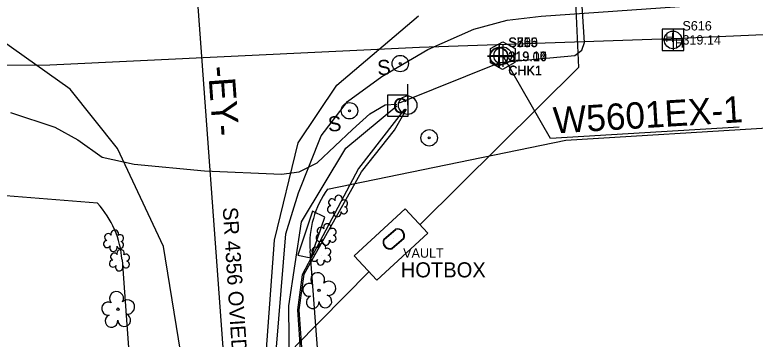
# Model space of a CAD drawing. Extents: x 2110969 to 2113691, y 670003 to 672285.
# Drawn here: x 2112129.5 to 2112326.2, y 670380.3 to 670466.5 of the extents above; entities that cross this region are included whole.
import ezdxf

# ---------------------------------------------------------------- set-up
doc = ezdxf.new("R2010")
doc.units = 0
for name, color, linetype in [('Cogo Default Point CELL', 7, 'Continuous'), ('COGO Default Point Elevation', 7, 'Continuous'), ('COGO Default Point Number', 7, 'Continuous'), ('Default', 7, 'Continuous'), ('Default Symbol CELL', 7, 'Continuous'), ('Default Symbol Cogo Comment', 7, 'Continuous'), ('Default Symbol Cogo Elevation', 7, 'Continuous'), ('Default Symbol Cogo Number', 7, 'Continuous'), ('Exist Horizontal Alignment', 7, 'Continuous'), ('Exist Horizontal Alignment Direction Label', 7, 'Continuous'), ('Exist Horizontal Baseline Alignment Station Label', 7, 'Continuous'), ('Exist Other Culture Anchor (Guy Wire) CELL', 7, 'Continuous'), ('Exist Other Culture Sign Text', 7, 'Continuous'), ('Exist Right of Way Line', 7, 'Continuous'), ('Exist Right of Way Symbol CELL', 7, 'Continuous'), ('Exist Roads EOP', 7, 'Continuous'), ('Exist Roads EOP Text', 7, 'Continuous'), ('Exist Utilities Power Pole CELL', 7, 'Continuous'), ('Exist Utilities Power UG Cable SUE LOS B', 7, 'Continuous'), ('Exist Utilities Telephone Hand Hole CELL', 7, 'Continuous'), ('Exist Utilities Telephone UG Cable SUE LOS B', 7, 'Continuous'), ('Exist Utilities Telephone UG FO SUE LOS B', 7, 'Continuous'), ('Exist Utilities TV Pedestal CELL', 7, 'Continuous'), ('Exist Utilities TV UG Cable SUE LOS B', 7, 'Continuous'), ('Exist Utilities Water Meter CELL', 7, 'Continuous'), ('Exist Utilities Water Meter Cogo Comment', 7, 'Continuous'), ('Exist Utilities Water Meter Text', 7, 'Continuous'), ('Exist Utilities Water UG Line SUE LOS B', 7, 'Continuous'), ('Exist Utilities Water UG Line SUE LOS C', 7, 'Continuous'), ('Exist Vegetation Hedge Row', 7, 'Continuous'), ('Exist Vegetation Shrub CELL', 7, 'Continuous'), ('Exist Vegetation Tree CELL', 7, 'Continuous')]:
    doc.layers.add(name, color=color, linetype=linetype)

msp = doc.modelspace()

# ---------------------------------------------------------------- linework, layer by layer
at = {"layer": 'Cogo Default Point CELL'}
for points in [[(2112304.4, 670462.84), (2112304.4, 670459.84)], [(2112301.4, 670459.84), (2112304.4, 670459.84)], [(2112304.4, 670459.84), (2112307.4, 670459.84)], [(2112304.4, 670459.84), (2112304.4, 670456.84)], [(2112259.14, 670458.65), (2112259.14, 670455.65)], [(2112256.14, 670455.65), (2112259.14, 670455.65)], [(2112259.14, 670455.65), (2112262.14, 670455.65)], [(2112259.14, 670455.65), (2112259.14, 670452.65)]]:
    msp.add_lwpolyline(points, dxfattribs=at)
for centre in [(2112304.4, 670459.84), (2112259.14, 670455.65)]:
    msp.add_circle(centre, 2.34, dxfattribs=at)
at = {"layer": 'Default'}
for centre, radius in [((2112231.9, 670453.55), 2.18), ((2112231.9, 670453.55), 0.24), ((2112218.41, 670440.99), 2.18), ((2112218.41, 670440.99), 0.24)]:
    msp.add_circle(centre, radius, dxfattribs=at)
at = {"layer": 'Default Symbol CELL'}
for points in [[(2112258.08, 670458.45), (2112258.08, 670452.45), (2112258.08, 670455.45), (2112261.08, 670455.45), (2112255.08, 670455.45)], [(2112258.13, 670458.52), (2112258.13, 670452.52), (2112258.13, 670455.52), (2112261.13, 670455.52), (2112255.13, 670455.52)], [(2112258.16, 670458.49), (2112258.16, 670452.49), (2112258.16, 670455.49), (2112261.16, 670455.49), (2112255.16, 670455.49)], [(2112258.17, 670458.4), (2112258.17, 670452.4), (2112258.17, 670455.4), (2112261.17, 670455.4), (2112255.17, 670455.4)]]:
    msp.add_lwpolyline(points, dxfattribs=at)
for centre in [(2112258.08, 670455.45), (2112258.13, 670455.52), (2112258.16, 670455.49), (2112258.17, 670455.4)]:
    msp.add_circle(centre, 2.34, dxfattribs=at)
at = {"layer": 'Exist Horizontal Alignment'}
msp.add_line((2112177.47, 670477.33), (2112189.48, 670313.22), dxfattribs=at)
at = {"layer": 'Exist Horizontal Baseline Alignment Station Label'}
for p, q in [((2112259.14, 670455.65), (2112259.14, 670455.65)), ((2112271.82, 670433.62), (2112259.14, 670455.65)), ((2112322.01, 670436.66), (2112271.82, 670433.62))]:
    msp.add_line(p, q, dxfattribs=at)
msp.add_lwpolyline([(2112255.91, 670457.52), (2112259.16, 670459.33), (2112262.41, 670457.54), (2112262.36, 670453.82), (2112259.11, 670451.93), (2112255.91, 670453.74)], close=True, dxfattribs=at)
at = {"layer": 'Exist Other Culture Anchor (Guy Wire) CELL'}
for radius in [2.18, 0.24]:
    msp.add_circle((2112239.6, 670433.79), radius, dxfattribs=at)
at = {"layer": 'Exist Right of Way Line'}
for p, q in [((2112275.95, 670433.2), (2113479.86, 670506.17)), ((2112207.92, 670403.72), (2112214.42, 670315.05)), ((2112157.96, 670401.32), (2112164.55, 670311.39))]:
    msp.add_line(p, q, dxfattribs=at)
at = {"layer": 'Exist Right of Way Symbol CELL'}
for p, q in [((2112212.59, 670420.18), (2112275.95, 670433.2)), ((2112151.44, 670416.41), (2112086.29, 670421.71))]:
    msp.add_line(p, q, dxfattribs=at)
for centre, start, end in [((2112232.86, 670405.54), 144.1594, 184.1881), ((2112133.03, 670399.49), 4.1881, 42.5871)]:
    msp.add_arc(centre, 25, start, end, dxfattribs=at)
at = {"layer": 'Exist Roads EOP'}
for points in [[(2112201.06, 670279.18), (2112198.59, 670327.05), (2112195.81, 670370.34), (2112198.47, 670406.61), (2112204.81, 670432.43), (2112215.03, 670447.81), (2112236.76, 670466.26)], [(2112180.52, 670277.9), (2112178.23, 670325.1), (2112174.12, 670373.25), (2112168.98, 670404.94), (2112156.8, 670430.96), (2112144.18, 670446.78), (2112125.88, 670459.79)]]:
    msp.add_lwpolyline(points, dxfattribs=at)
at = {"layer": 'Exist Utilities Power Pole CELL'}
for q in [(2112233.88, 670448.11), (2112233.88, 670442.48)]:
    msp.add_line((2112233.88, 670442.48), q, dxfattribs=at)
msp.add_circle((2112233.88, 670442.48), 2.45, dxfattribs=at)
at = {"layer": 'Exist Utilities Power UG Cable SUE LOS B'}
for points in [[(2112233.05, 670441.4), (2112220.78, 670425.67), (2112205.82, 670397.38), (2112204.62, 670388.05), (2112208.05, 670336.71), (2112208.66, 670271.01)], [(2112233.05, 670441.4), (2112220.78, 670425.67), (2112205.82, 670397.38), (2112204.62, 670388.05), (2112208.05, 670336.71), (2112208.66, 670271.01)], [(2112209.36, 670270.82), (2112208.67, 670336.72), (2112205.07, 670388.08), (2112206.39, 670397.58), (2112221.58, 670424.72), (2112230.37, 670435.85), (2112233.53, 670441.43)], [(2112209.36, 670270.82), (2112208.67, 670336.72), (2112205.07, 670388.08), (2112206.39, 670397.58), (2112221.58, 670424.72), (2112230.37, 670435.85), (2112233.53, 670441.43)]]:
    msp.add_lwpolyline(points, dxfattribs=at)
at = {"layer": 'Exist Utilities Telephone Hand Hole CELL'}
for p, q in [((2112301.54, 670462.71), (2112301.54, 670456.98)), ((2112307.27, 670462.71), (2112301.54, 670462.71)), ((2112301.54, 670462.71), (2112301.54, 670456.98)), ((2112307.27, 670462.71), (2112301.54, 670462.71)), ((2112307.27, 670456.98), (2112307.27, 670462.71)), ((2112307.27, 670456.98), (2112307.27, 670462.71)), ((2112304.4, 670459.84), (2112304.4, 670459.84)), ((2112304.4, 670459.84), (2112304.4, 670459.84)), ((2112301.54, 670456.98), (2112307.27, 670456.98)), ((2112301.54, 670456.98), (2112307.27, 670456.98))]:
    msp.add_line(p, q, dxfattribs=at)
at = {"layer": 'Exist Utilities Telephone UG Cable SUE LOS B'}
msp.add_lwpolyline([(2112175.93, 670269.83), (2112173.6, 670310.7), (2112175.12, 670313.54), (2112178.07, 670315.08), (2112188.21, 670315.86), (2112197.67, 670317.03), (2112199.38, 670318.43), (2112200.38, 670321.44), (2112198.48, 670355.55), (2112199.04, 670378.12), (2112201.51, 670408.23), (2112204.82, 670419.16), (2112210.89, 670434.36), (2112217.86, 670443.43), (2112227.03, 670450.14), (2112239.25, 670457.25), (2112251.47, 670462.65), (2112260.33, 670465.12), (2112269.39, 670466.11), (2112308.69, 670468.9)], dxfattribs=at)
msp.add_lwpolyline([(2112175.93, 670269.83), (2112173.6, 670310.7), (2112175.12, 670313.54), (2112178.07, 670315.08), (2112188.21, 670315.86), (2112197.67, 670317.03), (2112199.38, 670318.43), (2112200.38, 670321.44), (2112198.48, 670355.55), (2112199.04, 670378.12), (2112201.51, 670408.23), (2112204.82, 670419.16), (2112210.89, 670434.36), (2112217.86, 670443.43), (2112227.03, 670450.14), (2112239.25, 670457.25), (2112251.47, 670462.65), (2112260.33, 670465.12), (2112269.39, 670466.11), (2112308.69, 670468.9)], dxfattribs=at)
at = {"layer": 'Exist Utilities Telephone UG FO SUE LOS B'}
msp.add_lwpolyline([(2111579.85, 670418.18), (2111631.45, 670423.41), (2111740.38, 670432.81), (2111885.62, 670444.53), (2111926.38, 670441.18), (2111977.11, 670441.9), (2112063.2, 670445.72), (2112109.68, 670453.08), (2112138.77, 670453.18), (2112237, 670457.87), (2112306.5, 670460.33), (2112380.27, 670463.6), (2112482.83, 670468.65), (2112529.94, 670475.11), (2112581.42, 670479.39), (2112613.55, 670486.14), (2112667.68, 670491.25), (2112816.71, 670501.11)], dxfattribs=at)
msp.add_lwpolyline([(2111579.85, 670418.18), (2111631.45, 670423.41), (2111740.38, 670432.81), (2111885.62, 670444.53), (2111926.38, 670441.18), (2111977.11, 670441.9), (2112063.2, 670445.72), (2112109.68, 670453.08), (2112138.77, 670453.18), (2112237, 670457.87), (2112306.5, 670460.33), (2112380.27, 670463.6), (2112482.83, 670468.65), (2112529.94, 670475.11), (2112581.42, 670479.39), (2112613.55, 670486.14), (2112667.68, 670491.25), (2112816.71, 670501.11)], dxfattribs=at)
at = {"layer": 'Exist Utilities TV Pedestal CELL'}
msp.add_line((2112231.27, 670442.36), (2112231.27, 670442.36), dxfattribs=at)
msp.add_line((2112231.27, 670442.36), (2112231.27, 670442.36), dxfattribs=at)
msp.add_lwpolyline([(2112228.49, 670439.58), (2112234.04, 670439.58), (2112234.04, 670445.13), (2112228.49, 670445.13), (2112228.49, 670439.58)], dxfattribs=at)
msp.add_lwpolyline([(2112228.49, 670439.58), (2112234.04, 670439.58), (2112234.04, 670445.13), (2112228.49, 670445.13), (2112228.49, 670439.58)], dxfattribs=at)
at = {"layer": 'Exist Utilities TV UG Cable SUE LOS B'}
for points in [[(2112231.71, 670443.13), (2112258.41, 670453.87), (2112278.28, 670455.71), (2112280.15, 670457.13), (2112280.89, 670459.11), (2112278, 670503.62), (2112278.21, 670504.92)], [(2112231.71, 670443.13), (2112258.41, 670453.87), (2112278.28, 670455.71), (2112280.15, 670457.13), (2112280.89, 670459.11), (2112278, 670503.62), (2112278.21, 670504.92)], [(2112128.34, 670440.55), (2112140.14, 670436.6), (2112146.21, 670433.28), (2112152.67, 670428.63), (2112161.15, 670426.83), (2112179.84, 670425.01), (2112200.32, 670424.12), (2112205.04, 670424.75), (2112209.79, 670427.15), (2112219.23, 670436), (2112223.84, 670440.18), (2112227.89, 670442.57), (2112231, 670442.71)], [(2112128.34, 670440.55), (2112140.14, 670436.6), (2112146.21, 670433.28), (2112152.67, 670428.63), (2112161.15, 670426.83), (2112179.84, 670425.01), (2112200.32, 670424.12), (2112205.04, 670424.75), (2112209.79, 670427.15), (2112219.23, 670436), (2112223.84, 670440.18), (2112227.89, 670442.57), (2112231, 670442.71)], [(2112205.6, 670270.18), (2112202.8, 670336.45), (2112202.26, 670389.09), (2112205.7, 670411.45), (2112217.42, 670431.05), (2112231.02, 670442.32)], [(2112205.6, 670270.18), (2112202.8, 670336.45), (2112202.26, 670389.09), (2112205.7, 670411.45), (2112217.42, 670431.05), (2112231.02, 670442.32)]]:
    msp.add_lwpolyline(points, dxfattribs=at)
at = {"layer": 'Exist Utilities Water Meter CELL'}
msp.add_line((2112230.18, 670406.92), (2112230.18, 670406.92), dxfattribs=at)
msp.add_line((2112230.18, 670406.92), (2112230.18, 670406.92), dxfattribs=at)
msp.add_lwpolyline([(2112225.64, 670395.93), (2112239.2, 670408.42), (2112233.19, 670414.94), (2112219.64, 670402.44)], close=True, dxfattribs=at)
msp.add_lwpolyline([(2112225.64, 670395.93), (2112239.2, 670408.42), (2112233.19, 670414.94), (2112219.64, 670402.44)], close=True, dxfattribs=at)
for points in [[(2112227.53, 670406.87), (2112230.62, 670409.53)], [(2112227.53, 670406.87), (2112230.62, 670409.53)], [(2112227.62, 670406.77), (2112230.71, 670409.43)], [(2112227.62, 670406.77), (2112230.71, 670409.43)], [(2112232.75, 670407.07), (2112229.64, 670404.39)], [(2112232.75, 670407.07), (2112229.64, 670404.39)], [(2112232.84, 670406.96), (2112229.73, 670404.28)], [(2112232.84, 670406.96), (2112229.73, 670404.28)]]:
    msp.add_lwpolyline(points, dxfattribs=at)
for centre, radius, start, end in [((2112231.16, 670407.76), 1.86, 334.4518, 107.1119), ((2112231.16, 670407.76), 1.86, 334.4518, 107.1119), ((2112231.17, 670407.77), 1.73, 335.9307, 105.6763), ((2112231.17, 670407.77), 1.73, 335.9307, 105.6763), ((2112229.2, 670406.06), 1.86, 153.9815, 286.7829), ((2112229.2, 670406.06), 1.86, 153.9815, 286.7829), ((2112229.21, 670406.07), 1.73, 156.1044, 284.5858), ((2112229.21, 670406.07), 1.73, 156.1044, 284.5858)]:
    msp.add_arc(centre, radius, start, end, dxfattribs=at)
at = {"layer": 'Exist Utilities Water UG Line SUE LOS B'}
msp.add_lwpolyline([(2112277.16, 670499.37), (2112279.25, 670452.52), (2112237.22, 670410.72)], dxfattribs=at)
msp.add_lwpolyline([(2112277.16, 670499.37), (2112279.25, 670452.52), (2112237.22, 670410.72)], dxfattribs=at)
at = {"layer": 'Exist Utilities Water UG Line SUE LOS C'}
msp.add_lwpolyline([(2112223.66, 670398.22), (2112203.95, 670378.32), (2112204.71, 670343.42), (2112207.65, 670271.32)], dxfattribs=at)
msp.add_lwpolyline([(2112223.66, 670398.22), (2112203.95, 670378.32), (2112204.71, 670343.42), (2112207.65, 670271.32)], dxfattribs=at)
at = {"layer": 'Exist Vegetation Hedge Row'}
msp.add_lwpolyline([(2112204.69, 670402.61), (2112208.12, 670401.92), (2112211.9, 670412.7), (2112208.6, 670414.33), (2112204.69, 670402.61)], dxfattribs=at)
at = {"layer": 'Exist Vegetation Shrub CELL'}
for p, q in [((2112215.3, 670415.48), (2112215.3, 670415.48)), ((2112212.28, 670407.94), (2112212.28, 670407.94)), ((2112155.79, 670406.25), (2112155.79, 670406.25)), ((2112210.87, 670402.63), (2112210.87, 670402.63)), ((2112157.36, 670401.07), (2112157.36, 670401.07))]:
    msp.add_line(p, q, dxfattribs=at)
for centre, radius, start, end in [((2112215.53, 670417.52), 0.99, 334.8391, 200.4717), ((2112213.82, 670416.61), 0.968, 35.8908, 245.4216), ((2112216.98, 670416.35), 0.929, 284.4567, 126.0861), ((2112213.5, 670414.78), 0.955, 95.1099, 327.9534), ((2112215.18, 670413.8), 0.984, 151.2797, 21.387), ((2112216.94, 670414.55), 0.937, 204.9913, 73.4601), ((2112212.51, 670409.98), 0.99, 334.8391, 200.4717), ((2112156.02, 670408.3), 0.99, 334.8391, 200.4717), ((2112210.8, 670409.06), 0.968, 35.8908, 245.4216), ((2112213.96, 670408.8), 0.929, 284.4567, 126.0861), ((2112153.99, 670405.55), 0.955, 95.1099, 327.9534), ((2112154.31, 670407.38), 0.968, 35.8908, 245.4216), ((2112157.46, 670407.12), 0.929, 284.4567, 126.0861), ((2112210.48, 670407.23), 0.955, 95.1099, 327.9534), ((2112212.16, 670406.25), 0.984, 151.2797, 21.387), ((2112213.92, 670407.01), 0.937, 204.9913, 73.4601), ((2112155.66, 670404.57), 0.984, 151.2797, 21.387), ((2112157.43, 670405.33), 0.937, 204.9913, 73.4601), ((2112209.39, 670403.76), 0.968, 35.8908, 245.4216), ((2112211.1, 670404.68), 0.99, 334.8391, 200.4717), ((2112212.54, 670403.5), 0.929, 284.4567, 126.0861), ((2112155.88, 670402.19), 0.968, 35.8908, 245.4216), ((2112157.59, 670403.11), 0.99, 334.8391, 200.4717), ((2112159.03, 670401.93), 0.929, 284.4567, 126.0861), ((2112209.07, 670401.93), 0.955, 95.1099, 327.9534), ((2112212.51, 670401.71), 0.937, 204.9913, 73.4601), ((2112155.56, 670400.36), 0.955, 95.1099, 327.9534), ((2112159, 670400.14), 0.937, 204.9913, 73.4601), ((2112210.74, 670400.95), 0.984, 151.2797, 21.387), ((2112157.23, 670399.38), 0.984, 151.2797, 21.387)]:
    msp.add_arc(centre, radius, start, end, dxfattribs=at)
at = {"layer": 'Exist Vegetation Tree CELL'}
for p, q in [((2112210.34, 670393.22), (2112210.34, 670393.22)), ((2112156.87, 670388.23), (2112156.87, 670388.23))]:
    msp.add_line(p, q, dxfattribs=at)
for centre in [(2112210.34, 670393.22), (2112156.87, 670388.23)]:
    msp.add_circle(centre, 0.326, dxfattribs=at)
for centre, radius, start, end in [((2112209.96, 670396.09), 1.86, 330.1651, 219.7134), ((2112207.74, 670393.37), 1.73, 62.6636, 279.3457), ((2112212.89, 670393.8), 1.9, 257.1011, 134.1999), ((2112156.49, 670391.1), 1.86, 330.1651, 219.7134), ((2112159.42, 670388.82), 1.9, 257.1011, 134.1999), ((2112208.64, 670390.1), 1.69, 111.5671, 6.231), ((2112212.01, 670390.32), 1.7, 181.2822, 74.56), ((2112154.27, 670388.38), 1.73, 62.6636, 279.3457), ((2112158.55, 670385.33), 1.7, 181.2822, 74.56), ((2112155.17, 670385.11), 1.69, 111.5671, 6.231)]:
    msp.add_arc(centre, radius, start, end, dxfattribs=at)

# ---------------------------------------------------------------- texts
at = {"layer": 'COGO Default Point Elevation'}
msp.add_text('319.14', height=2.5, dxfattribs=at).set_placement((2112306.9, 670458.59))
at = {"layer": 'COGO Default Point Number'}
msp.add_text('S616', height=2.5, dxfattribs=at).set_placement((2112306.9, 670462.34))
at = {"layer": 'Default Symbol Cogo Comment'}
for p in [(2112260.58, 670450.45), (2112260.63, 670450.52), (2112260.66, 670450.49), (2112260.67, 670450.4)]:
    msp.add_text('CHK1', height=2.5, dxfattribs=at).set_placement(p)
at = {"layer": 'Default Symbol Cogo Elevation'}
for s, p in [('319.07', (2112260.58, 670454.2)), ('319.10', (2112260.63, 670454.27)), ('319.14', (2112260.66, 670454.24)), ('319.10', (2112260.67, 670454.15))]:
    msp.add_text(s, height=2.5, dxfattribs=at).set_placement(p)
at = {"layer": 'Default Symbol Cogo Number'}
for s, p in [('S715', (2112260.58, 670457.95)), ('S556', (2112260.63, 670458.02)), ('S200', (2112260.66, 670457.99)), ('S555', (2112260.67, 670457.9))]:
    msp.add_text(s, height=2.5, dxfattribs=at).set_placement(p)
at = {"layer": 'Exist Horizontal Alignment Direction Label'}
msp.add_text('-EY-  ', height=7, rotation=274.1881, dxfattribs=at).set_placement((2112180.78, 670452.72))
at = {"layer": 'Exist Horizontal Baseline Alignment Station Label'}
msp.add_text('W5601EX-1', height=7, rotation=3.4682, dxfattribs=at).set_placement((2112272.74, 670434.93))
at = {"layer": 'Exist Other Culture Sign Text'}
for p in [(2112225.91, 670450.41), (2112212.81, 670435.43)]:
    msp.add_text('S', height=4, rotation=3.5501, dxfattribs=at).set_placement(p)
at = {"layer": 'Exist Roads EOP Text'}
msp.add_text("SR 4356 OVIEDO DR  21' BST", height=4, rotation=273.6692, dxfattribs=at).set_placement((2112184.71, 670415.25))
at = {"layer": 'Exist Utilities Telephone Hand Hole CELL'}
for p in [(2112302.32, 670459.25), (2112302.32, 670459.25), (2112304.89, 670457.79), (2112304.89, 670457.79)]:
    msp.add_text('H', height=2.5, dxfattribs=at).set_placement(p)
at = {"layer": 'Exist Utilities TV Pedestal CELL'}
msp.add_text('C', height=4, dxfattribs=at).set_placement((2112229.96, 670440.36))
msp.add_text('C', height=4, dxfattribs=at).set_placement((2112229.96, 670440.36))
at = {"layer": 'Exist Utilities Water Meter Cogo Comment'}
msp.add_text('VAULT', height=2.5, dxfattribs=at).set_placement((2112232.68, 670401.92))
at = {"layer": 'Exist Utilities Water Meter Text'}
msp.add_text('HOTBOX', height=4, dxfattribs=at).set_placement((2112232.04, 670396.7))

doc.saveas('drawing.dxf')
